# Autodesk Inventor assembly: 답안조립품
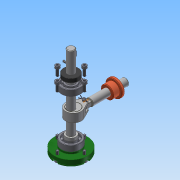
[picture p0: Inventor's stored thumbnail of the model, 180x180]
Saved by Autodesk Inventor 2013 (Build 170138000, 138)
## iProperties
Created: 2016-02
Part Number: 답안조립품
Document SubType Name: Assembly
Designer: Administrator
Author: Administrator
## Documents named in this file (16)
- C:\Users\Administrator\Desktop\460212V1017\답안조립품.iam
- C:\Users\Administrator\Desktop\460212V1017\본체.ipt
- C:\Users\Administrator\Desktop\460212V1017\뒤커버.ipt
- C:\Users\Administrator\Desktop\460212V1017\링크.ipt
- C:\Users\Administrator\Desktop\460212V1017\베어링 12 x 32 x 10.ipt
- C:\Users\Administrator\Desktop\460212V1017\앞커버.ipt
- C:\Users\Administrator\Desktop\460212V1017\오일실 12 25 7.ipt
- C:\Users\Administrator\Desktop\460212V1017\편심축.ipt
- C:\Users\Administrator\Desktop\460212V1017\키 4 x 4 x 10.ipt
- C:\Users\Administrator\Desktop\460212V1017\V벨트풀리.ipt
- C:\Users\Administrator\Desktop\460212V1017\멈춤나사 M3x8.ipt
- C:\Users\Administrator\Desktop\460212V1017\부시.ipt
- C:\Users\Administrator\Desktop\460212V1017\슬라이드.ipt
- C:\Users\Administrator\Desktop\460212V1017\고정핀 1.2 x 10.ipt
- C:\Users\Administrator\Desktop\460212V1017\핀 5 x 18.ipt
- C:\Users\Administrator\Desktop\460212V1017\볼트 M4 x 12.ipt
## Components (11 placed, 4 different names)
1. V벨트풀리:1
2. 고정핀 1.2 x 10:1 — 플러쉬:1
3. 핀 5 x 18:1
4. ISO 4762 M4 x 12:1
5. ISO 4762 M4 x 12:3
6. ISO 4762 M4 x 12:4
7. ISO 4762 M4 x 12:5
8. ISO 4762 M4 x 12:2
9. ISO 4762 M4 x 12:6
10. ISO 4762 M4 x 12:7
11. ISO 4762 M4 x 12:8
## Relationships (1: Flush 1)
- 플러쉬:1 [Flush]: 고정핀 1.2 x 10:1
